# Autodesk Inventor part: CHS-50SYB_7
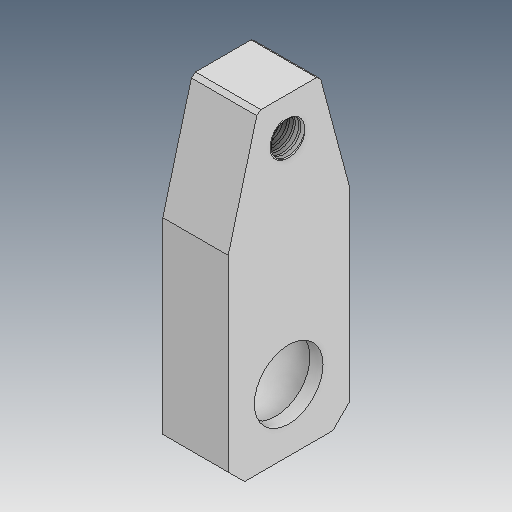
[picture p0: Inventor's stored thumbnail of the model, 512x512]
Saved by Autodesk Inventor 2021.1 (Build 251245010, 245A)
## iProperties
Created: 2019-04
Part Number: CHS-50SYB_7
Material: Ogólny
Document SubType Name: Modeling
Designer: user
Density: 1 g/cm^3
Appearance: Domyślna
Author: user
Revision Number: ÈÎºÎ
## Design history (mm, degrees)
feature "ÊäÈë1"
node "Bryła1"
